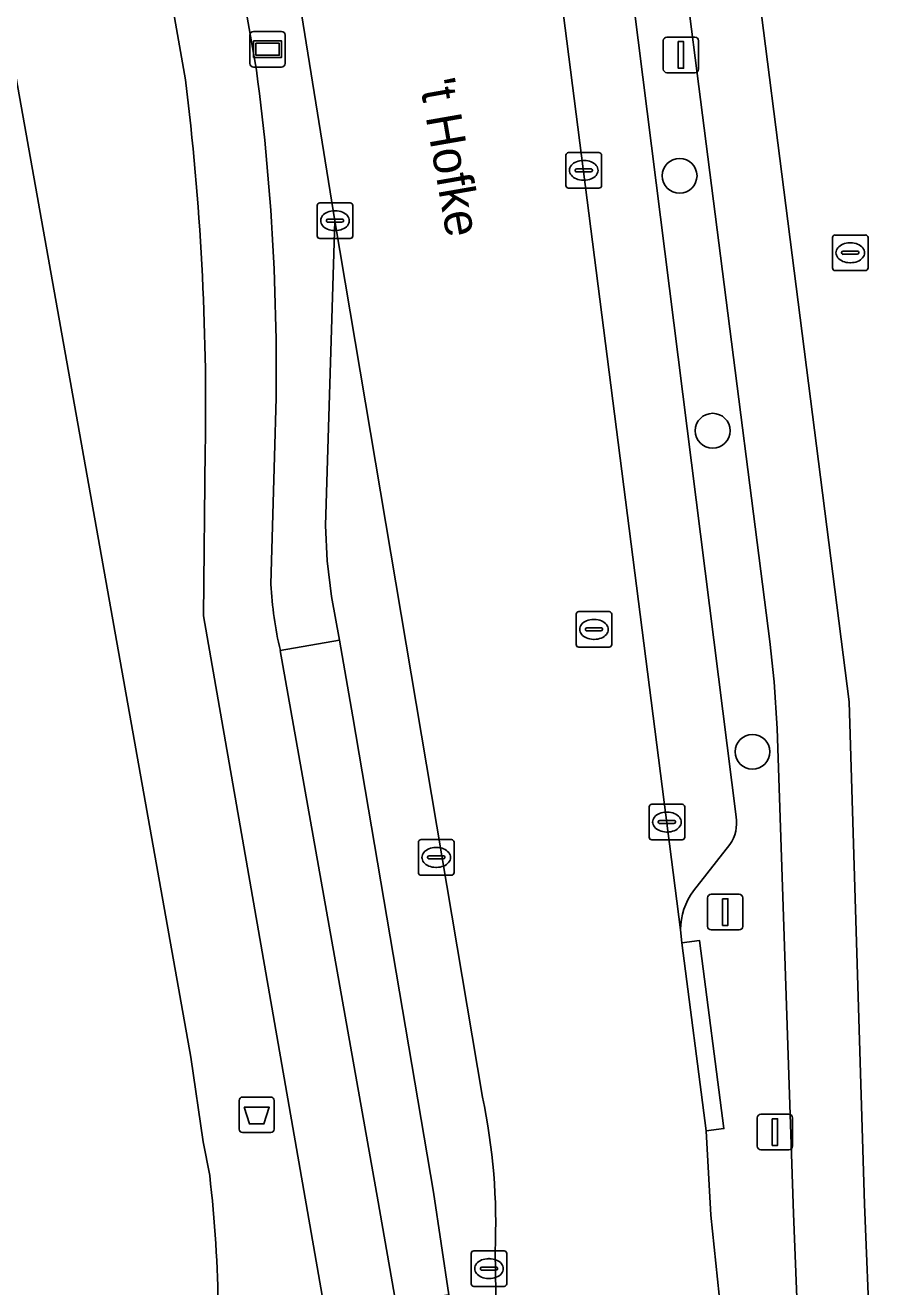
# Model space of a CAD drawing. Extents: x 162879 to 165540, y 384011 to 385181.
# Drawn here: x 164067.28 to 164091.19, y 384371.44 to 384406.9 of the extents above; entities that cross this region are included whole.
import ezdxf

# ---------------------------------------------------------------- set-up
doc = ezdxf.new("R2010")
doc.units = 0
for name, color, linetype in [('IMGEO_Afvalbak', 7, 'Continuous'), ('IMGEO_Boom', 7, 'Continuous'), ('IMGEO_Brandkraan', 7, 'Continuous'), ('IMGEO_Erf', 7, 'Continuous'), ('IMGEO_Fietspad_gesloten', 7, 'Continuous'), ('IMGEO_Kolk', 7, 'Continuous'), ('IMGEO_Lichtmast', 7, 'Continuous'), ('IMGEO_Openbare_ruimte_label', 7, 'Continuous'), ('IMGEO_Parkeervlak_open', 7, 'Continuous'), ('IMGEO_Rijbaan_lokaal_gesloten', 7, 'Continuous'), ('IMGEO_Rijbaan_lokaal_open', 7, 'Continuous'), ('IMGEO_Rioolput', 7, 'Continuous'), ('IMGEO_Verkeerseiland_open', 7, 'Continuous'), ('IMGEO_Verkeersregelinstallatiepaal', 7, 'Continuous'), ('IMGEO_Voetpad_open', 7, 'Continuous'), ('IMGEO_Wegwijzer', 7, 'Continuous')]:
    doc.layers.add(name, color=color, linetype=linetype)

msp = doc.modelspace()

# ---------------------------------------------------------------- linework, layer by layer
at = {"layer": 'IMGEO_Afvalbak'}
for p, q in [((164073.392, 384376.77), (164074.182, 384376.77)), ((164074.182, 384376.77), (164073.392, 384376.77)), ((164073.292, 384375.87), (164073.292, 384376.67)), ((164073.292, 384376.67), (164073.292, 384375.87)), ((164074.282, 384376.67), (164074.282, 384375.87)), ((164074.282, 384375.87), (164074.282, 384376.67)), ((164074.182, 384375.77), (164073.392, 384375.77)), ((164073.392, 384375.77), (164074.182, 384375.77))]:
    msp.add_line(p, q, dxfattribs=at)
msp.add_lwpolyline([(164073.435, 384376.484), (164074.139, 384376.484), (164073.99, 384376.014), (164073.584, 384376.014), (164073.435, 384376.484)], dxfattribs=at)
for centre, start, end in [((164073.392, 384376.67), 90, 180), ((164073.392, 384376.67), 90, 180), ((164074.182, 384376.67), 0, 90), ((164074.182, 384376.67), 360, 90), ((164073.392, 384375.87), 180, 270), ((164073.392, 384375.87), 180, 270), ((164074.182, 384375.87), 270, 0), ((164074.182, 384375.87), 270, 0)]:
    msp.add_arc(centre, 0.1, start, end, dxfattribs=at)
at = {"layer": 'IMGEO_Boom'}
for centre in [(164085.677, 384402.67), (164086.606, 384395.503), (164087.725, 384386.477)]:
    msp.add_circle(centre, 0.489, dxfattribs=at)
at = {"layer": 'IMGEO_Brandkraan'}
for p, q in [((164089.973, 384400.079), (164089.973, 384400.931)), ((164090.048, 384401.005), (164090.9, 384401.005)), ((164090.974, 384400.931), (164090.974, 384400.079)), ((164090.232, 384400.499), (164090.232, 384400.511)), ((164090.275, 384400.548), (164090.673, 384400.548)), ((164090.461, 384400.785), (164090.486, 384400.785)), ((164090.716, 384400.511), (164090.716, 384400.499)), ((164090.67, 384400.462), (164090.272, 384400.462)), ((164090.484, 384400.225), (164090.459, 384400.225)), ((164090.9, 384400.005), (164090.048, 384400.005))]:
    msp.add_line(p, q, dxfattribs=at)
for points in [[(164089.973, 384400.079), (164089.973, 384400.931)], [(164090.048, 384401.005), (164090.9, 384401.005)], [(164090.974, 384400.931), (164090.974, 384400.079)], [(164090.9, 384400.005), (164090.048, 384400.005)]]:
    msp.add_lwpolyline(points, dxfattribs=at)
for centre, radius, start, end in [((164090.05, 384400.929), 0.0765, 91.552, 178.448), ((164090.05, 384400.929), 0.0765, 91.552, 178.448), ((164090.898, 384400.929), 0.0765, 1.552, 88.448), ((164090.898, 384400.929), 0.0765, 1.552, 88.448), ((164090.272, 384400.508), 0.0403, 85.8775, 175.7526), ((164090.269, 384400.498), 0.0366, 178.938, 274.7102), ((164090.673, 384400.505), 0.043, 264.8664, 352.4533), ((164090.677, 384400.51), 0.0386, 1.7309, 96.639), ((164090.05, 384400.081), 0.0765, 181.552, 268.448), ((164090.05, 384400.081), 0.0765, 181.552, 268.448), ((164090.898, 384400.081), 0.0765, 271.552, 358.448), ((164090.898, 384400.081), 0.0765, 271.552, 358.448)]:
    msp.add_arc(centre, radius, start, end, dxfattribs=at)
for centre, major_axis, ratio, start_param, end_param in [((164090.46, 384400.505), (-0.387, 0.002), 0.722429, 4.712389, 7.853982), ((164090.485, 384400.505), (-0.39, 0.002), 0.717154, 1.570796, 4.712389)]:
    msp.add_ellipse(centre, major_axis=major_axis, ratio=ratio, start_param=start_param, end_param=end_param, dxfattribs=at)
at = {"layer": 'IMGEO_Erf'}
msp.add_lwpolyline([(164072.467, 384374.563), (164072.28, 384375.515), (164071.935, 384377.894), (164066.095, 384410.579)], dxfattribs=at)
msp.add_arc((164038.439, 384370.544), 34.264, 353.9227, 6.7367, dxfattribs=at)
at = {"layer": 'IMGEO_Fietspad_gesloten'}
for points in [[(164073.781, 384405.638), (164070.271, 384425.587), (164068.28, 384425.24), (164071.787, 384405.368)], [(164083.909, 384423.215), (164088.215, 384389.576), (164088.332, 384388.439), (164088.421, 384387.131), (164088.88, 384373.493), (164089.214, 384364.987), (164089.693, 384360.397), (164090.613, 384357.272), (164091.093, 384356.072)], [(164091.191, 384365.926), (164090.87, 384373.758), (164090.447, 384387.88), (164086.087, 384422.038)], [(164072.343, 384394.961), (164072.288, 384390.302), (164076.244, 384367.644), (164077.618, 384359.772), (164077.76, 384358.65), (164077.795, 384357.337)], [(164074.188, 384391.189), (164074.3, 384395.108)], [(164079.645, 384355.684), (164079.809, 384356.913), (164079.609, 384360.107), (164077.698, 384370.985), (164077.2, 384373.82), (164074.452, 384389.325)]]:
    msp.add_lwpolyline(points, dxfattribs=at)
for centre, radius, start, end in [((164010.853, 384397.259), 63.484, 358.05863, 7.58476), ((163997.018, 384396.155), 75.334, 359.0918, 7.02451), ((164084.638, 384391.718), 10.463, 182.8997, 193.2228)]:
    msp.add_arc(centre, radius, start, end, dxfattribs=at)
at = {"layer": 'IMGEO_Kolk'}
for p, q in [((164082.482, 384402.397), (164082.482, 384403.249)), ((164082.557, 384403.323), (164083.409, 384403.323)), ((164082.97, 384403.103), (164082.995, 384403.103)), ((164083.483, 384403.249), (164083.483, 384402.397)), ((164082.741, 384402.817), (164082.741, 384402.829)), ((164083.179, 384402.78), (164082.781, 384402.78)), ((164082.784, 384402.866), (164083.182, 384402.866)), ((164083.225, 384402.829), (164083.225, 384402.817)), ((164083.409, 384402.323), (164082.557, 384402.323)), ((164082.993, 384402.543), (164082.968, 384402.543)), ((164075.488, 384400.982), (164075.488, 384401.834)), ((164075.563, 384401.908), (164076.415, 384401.908)), ((164075.976, 384401.688), (164076.001, 384401.688)), ((164076.489, 384401.834), (164076.489, 384400.982)), ((164075.747, 384401.402), (164075.747, 384401.414)), ((164076.185, 384401.365), (164075.787, 384401.365)), ((164075.79, 384401.451), (164076.188, 384401.451)), ((164076.231, 384401.414), (164076.231, 384401.402)), ((164076.415, 384400.908), (164075.563, 384400.908)), ((164075.999, 384401.128), (164075.974, 384401.128)), ((164084.819, 384384.074), (164084.819, 384384.926)), ((164084.894, 384385), (164085.746, 384385)), ((164085.82, 384384.926), (164085.82, 384384.074)), ((164085.121, 384384.543), (164085.519, 384384.543)), ((164085.307, 384384.78), (164085.332, 384384.78)), ((164085.078, 384384.494), (164085.078, 384384.506)), ((164085.516, 384384.457), (164085.118, 384384.457)), ((164085.33, 384384.22), (164085.305, 384384.22)), ((164085.562, 384384.506), (164085.562, 384384.494)), ((164078.334, 384383.08), (164078.334, 384383.932)), ((164078.409, 384384.006), (164079.261, 384384.006)), ((164079.335, 384383.932), (164079.335, 384383.08)), ((164085.746, 384384), (164084.894, 384384)), ((164078.593, 384383.5), (164078.593, 384383.512)), ((164078.636, 384383.549), (164079.034, 384383.549)), ((164078.822, 384383.786), (164078.847, 384383.786)), ((164079.077, 384383.512), (164079.077, 384383.5)), ((164079.031, 384383.463), (164078.633, 384383.463)), ((164078.845, 384383.226), (164078.82, 384383.226)), ((164079.261, 384383.006), (164078.409, 384383.006)), ((164079.817, 384371.52), (164079.817, 384372.372)), ((164079.892, 384372.446), (164080.744, 384372.446)), ((164080.305, 384372.226), (164080.33, 384372.226)), ((164080.818, 384372.372), (164080.818, 384371.52)), ((164080.076, 384371.94), (164080.076, 384371.952)), ((164080.514, 384371.903), (164080.116, 384371.903)), ((164080.119, 384371.989), (164080.517, 384371.989)), ((164080.56, 384371.952), (164080.56, 384371.94)), ((164080.744, 384371.446), (164079.892, 384371.446)), ((164080.328, 384371.666), (164080.303, 384371.666))]:
    msp.add_line(p, q, dxfattribs=at)
for points in [[(164082.482, 384402.397), (164082.482, 384403.249)], [(164082.557, 384403.323), (164083.409, 384403.323)], [(164083.483, 384403.249), (164083.483, 384402.397)], [(164083.409, 384402.323), (164082.557, 384402.323)], [(164075.488, 384400.982), (164075.488, 384401.834)], [(164075.563, 384401.908), (164076.415, 384401.908)], [(164076.489, 384401.834), (164076.489, 384400.982)], [(164076.415, 384400.908), (164075.563, 384400.908)], [(164084.819, 384384.074), (164084.819, 384384.926)], [(164084.894, 384385), (164085.746, 384385)], [(164085.82, 384384.926), (164085.82, 384384.074)], [(164078.334, 384383.08), (164078.334, 384383.932)], [(164078.409, 384384.006), (164079.261, 384384.006)], [(164079.335, 384383.932), (164079.335, 384383.08)], [(164085.746, 384384), (164084.894, 384384)], [(164079.261, 384383.006), (164078.409, 384383.006)], [(164079.817, 384371.52), (164079.817, 384372.372)], [(164079.892, 384372.446), (164080.744, 384372.446)], [(164080.818, 384372.372), (164080.818, 384371.52)], [(164080.744, 384371.446), (164079.892, 384371.446)]]:
    msp.add_lwpolyline(points, dxfattribs=at)
for centre, radius, start, end in [((164082.559, 384403.247), 0.0765, 91.552, 178.448), ((164082.559, 384403.247), 0.0765, 91.552, 178.448), ((164083.407, 384403.247), 0.0765, 1.552, 88.448), ((164083.407, 384403.247), 0.0765, 1.552, 88.448), ((164082.781, 384402.826), 0.0403, 85.8775, 175.7526), ((164082.778, 384402.816), 0.0366, 178.938, 274.7102), ((164083.182, 384402.823), 0.043, 264.8664, 352.4533), ((164083.186, 384402.828), 0.0386, 1.7309, 96.639), ((164082.559, 384402.399), 0.0765, 181.552, 268.448), ((164082.559, 384402.399), 0.0765, 181.552, 268.448), ((164083.407, 384402.399), 0.0765, 271.552, 358.448), ((164083.407, 384402.399), 0.0765, 271.552, 358.448), ((164075.565, 384401.832), 0.0765, 91.552, 178.448), ((164075.565, 384401.832), 0.0765, 91.552, 178.448), ((164076.413, 384401.832), 0.0765, 1.552, 88.448), ((164076.413, 384401.832), 0.0765, 1.552, 88.448), ((164075.787, 384401.411), 0.0403, 85.8775, 175.7526), ((164075.784, 384401.401), 0.0366, 178.938, 274.7102), ((164076.188, 384401.408), 0.043, 264.8664, 352.4533), ((164076.192, 384401.413), 0.0386, 1.7309, 96.639), ((164075.565, 384400.984), 0.0765, 181.552, 268.448), ((164075.565, 384400.984), 0.0765, 181.552, 268.448), ((164076.413, 384400.984), 0.0765, 271.552, 358.448), ((164076.413, 384400.984), 0.0765, 271.552, 358.448), ((164084.896, 384384.924), 0.0765, 91.552, 178.448), ((164084.896, 384384.924), 0.0765, 91.552, 178.448), ((164085.744, 384384.924), 0.0765, 1.552, 88.448), ((164085.744, 384384.924), 0.0765, 1.552, 88.448), ((164085.118, 384384.503), 0.0403, 85.8775, 175.7526), ((164085.523, 384384.505), 0.0386, 1.7309, 96.639), ((164085.115, 384384.493), 0.0366, 178.938, 274.7102), ((164085.519, 384384.5), 0.043, 264.8664, 352.4533), ((164078.411, 384383.93), 0.0765, 91.552, 178.448), ((164078.411, 384383.93), 0.0765, 91.552, 178.448), ((164079.259, 384383.93), 0.0765, 1.552, 88.448), ((164079.259, 384383.93), 0.0765, 1.552, 88.448), ((164084.896, 384384.076), 0.0765, 181.552, 268.448), ((164084.896, 384384.076), 0.0765, 181.552, 268.448), ((164085.744, 384384.076), 0.0765, 271.552, 358.448), ((164085.744, 384384.076), 0.0765, 271.552, 358.448), ((164078.633, 384383.509), 0.0403, 85.8775, 175.7526), ((164078.63, 384383.499), 0.0366, 178.938, 274.7102), ((164079.034, 384383.506), 0.043, 264.8664, 352.4533), ((164079.038, 384383.511), 0.0386, 1.7309, 96.639), ((164078.411, 384383.082), 0.0765, 181.552, 268.448), ((164078.411, 384383.082), 0.0765, 181.552, 268.448), ((164079.259, 384383.082), 0.0765, 271.552, 358.448), ((164079.259, 384383.082), 0.0765, 271.552, 358.448), ((164079.894, 384372.37), 0.0765, 91.552, 178.448), ((164079.894, 384372.37), 0.0765, 91.552, 178.448), ((164080.742, 384372.37), 0.0765, 1.552, 88.448), ((164080.742, 384372.37), 0.0765, 1.552, 88.448), ((164080.116, 384371.949), 0.0403, 85.8775, 175.7526), ((164080.113, 384371.939), 0.0366, 178.938, 274.7102), ((164080.517, 384371.946), 0.043, 264.8664, 352.4533), ((164080.521, 384371.951), 0.0386, 1.7309, 96.639), ((164079.894, 384371.522), 0.0765, 181.552, 268.448), ((164079.894, 384371.522), 0.0765, 181.552, 268.448), ((164080.742, 384371.522), 0.0765, 271.552, 358.448), ((164080.742, 384371.522), 0.0765, 271.552, 358.448)]:
    msp.add_arc(centre, radius, start, end, dxfattribs=at)
for centre, major_axis, ratio, start_param, end_param in [((164082.969, 384402.823), (-0.387, 0.002), 0.722429, 4.712389, 7.853982), ((164082.994, 384402.823), (-0.39, 0.002), 0.717154, 1.570796, 4.712389), ((164075.975, 384401.408), (-0.387, 0.002), 0.722429, 4.712389, 7.853982), ((164076, 384401.408), (-0.39, 0.002), 0.717154, 1.570796, 4.712389), ((164085.306, 384384.5), (-0.387, 0.002), 0.722429, 4.712389, 7.853982), ((164085.331, 384384.5), (-0.39, 0.002), 0.717154, 1.570796, 4.712389), ((164078.821, 384383.506), (-0.387, 0.002), 0.722429, 4.712389, 7.853982), ((164078.846, 384383.506), (-0.39, 0.002), 0.717154, 1.570796, 4.712389), ((164080.304, 384371.946), (-0.387, 0.002), 0.722429, 4.712389, 7.853982), ((164080.329, 384371.946), (-0.39, 0.002), 0.717154, 1.570796, 4.712389)]:
    msp.add_ellipse(centre, major_axis=major_axis, ratio=ratio, start_param=start_param, end_param=end_param, dxfattribs=at)
at = {"layer": 'IMGEO_Lichtmast'}
for p, q in [((164085.319, 384406.568), (164086.109, 384406.568)), ((164086.109, 384406.568), (164085.319, 384406.568)), ((164085.219, 384405.668), (164085.219, 384406.468)), ((164085.219, 384406.468), (164085.219, 384405.668)), ((164086.209, 384406.468), (164086.209, 384405.668)), ((164086.209, 384405.668), (164086.209, 384406.468)), ((164086.109, 384405.568), (164085.319, 384405.568)), ((164085.319, 384405.568), (164086.109, 384405.568)), ((164087.861, 384375.386), (164087.861, 384376.186)), ((164087.861, 384376.186), (164087.861, 384375.386)), ((164087.961, 384376.286), (164088.751, 384376.286)), ((164088.751, 384376.286), (164087.961, 384376.286)), ((164088.851, 384376.186), (164088.851, 384375.386)), ((164088.851, 384375.386), (164088.851, 384376.186)), ((164088.751, 384375.286), (164087.961, 384375.286)), ((164087.961, 384375.286), (164088.751, 384375.286))]:
    msp.add_line(p, q, dxfattribs=at)
for points in [[(164085.639, 384406.443), (164085.789, 384406.443), (164085.789, 384405.693), (164085.639, 384405.693), (164085.639, 384406.443)], [(164088.281, 384376.161), (164088.431, 384376.161), (164088.431, 384375.411), (164088.281, 384375.411), (164088.281, 384376.161)]]:
    msp.add_lwpolyline(points, dxfattribs=at)
for centre, start, end in [((164085.319, 384406.468), 90, 180), ((164085.319, 384406.468), 90, 180), ((164086.109, 384406.468), 0, 90), ((164086.109, 384406.468), 360, 90), ((164085.319, 384405.668), 180, 270), ((164085.319, 384405.668), 180, 270), ((164086.109, 384405.668), 270, 0), ((164086.109, 384405.668), 270, 0), ((164087.961, 384376.186), 90, 180), ((164087.961, 384376.186), 90, 180), ((164088.751, 384376.186), 0, 90), ((164088.751, 384376.186), 360, 90), ((164087.961, 384375.386), 180, 270), ((164087.961, 384375.386), 180, 270), ((164088.751, 384375.386), 270, 0), ((164088.751, 384375.386), 270, 0)]:
    msp.add_arc(centre, 0.1, start, end, dxfattribs=at)
at = {"layer": 'IMGEO_Parkeervlak_open'}
for points in [[(164080.607, 384421.336), (164085.705, 384381.473)], [(164087.267, 384384.65), (164083.012, 384418.373)], [(164086.071, 384382.565), (164087.086, 384383.867)]]:
    msp.add_lwpolyline(points, dxfattribs=at)
for centre, radius, start, end in [((164086.212, 384384.481), 1.068, 324.8826, 9.0855), ((164087.483, 384381.484), 1.778, 142.5768, 180.3646)]:
    msp.add_arc(centre, radius, start, end, dxfattribs=at)
at = {"layer": 'IMGEO_Rijbaan_lokaal_gesloten'}
for points in [[(164071.827, 384426.866), (164071.993, 384425.884), (164073.176, 384418.869), (164075.989, 384401.408), (164080.136, 384376.77)], [(164080.489, 384372.432), (164080.558, 384368.374), (164087.023, 384368.952), (164086.558, 384373.446), (164086.427, 384375.821), (164085.739, 384381.108), (164085.705, 384381.473), (164080.607, 384421.336)]]:
    msp.add_lwpolyline(points, dxfattribs=at)
msp.add_arc((164063.395, 384373.224), 17.112, 357.346, 11.9582, dxfattribs=at)
at = {"layer": 'IMGEO_Rijbaan_lokaal_open'}
for points in [[(164075.989, 384401.408), (164075.722, 384392.841), (164075.765, 384391.847), (164075.895, 384390.844), (164076.113, 384389.61), (164076.492, 384387.459), (164078.76, 384374.096), (164079.187, 384371.205), (164079.617, 384368.29), (164080.558, 384368.374), (164080.489, 384372.432)], [(164080.136, 384376.77), (164075.989, 384401.408)]]:
    msp.add_lwpolyline(points, dxfattribs=at)
msp.add_arc((164063.395, 384373.224), 17.112, 357.346, 11.9582, dxfattribs=at)
at = {"layer": 'IMGEO_Rioolput'}
for p, q in [((164082.768, 384389.491), (164082.768, 384390.343)), ((164082.843, 384390.417), (164083.695, 384390.417)), ((164083.769, 384390.343), (164083.769, 384389.491)), ((164083.027, 384389.911), (164083.027, 384389.923)), ((164083.465, 384389.874), (164083.067, 384389.874)), ((164083.07, 384389.96), (164083.468, 384389.96)), ((164083.256, 384390.197), (164083.281, 384390.197)), ((164083.511, 384389.923), (164083.511, 384389.911)), ((164083.279, 384389.637), (164083.254, 384389.637)), ((164083.695, 384389.417), (164082.843, 384389.417))]:
    msp.add_line(p, q, dxfattribs=at)
for points in [[(164082.768, 384389.491), (164082.768, 384390.343)], [(164082.843, 384390.417), (164083.695, 384390.417)], [(164083.769, 384390.343), (164083.769, 384389.491)], [(164083.695, 384389.417), (164082.843, 384389.417)]]:
    msp.add_lwpolyline(points, dxfattribs=at)
for centre, radius, start, end in [((164082.845, 384390.341), 0.0765, 91.552, 178.448), ((164082.845, 384390.341), 0.0765, 91.552, 178.448), ((164083.693, 384390.341), 0.0765, 1.552, 88.448), ((164083.693, 384390.341), 0.0765, 1.552, 88.448), ((164083.067, 384389.92), 0.0403, 85.8775, 175.7526), ((164083.064, 384389.91), 0.0366, 178.938, 274.7102), ((164083.468, 384389.917), 0.043, 264.8664, 352.4533), ((164083.472, 384389.922), 0.0386, 1.7309, 96.639), ((164082.845, 384389.493), 0.0765, 181.552, 268.448), ((164082.845, 384389.493), 0.0765, 181.552, 268.448), ((164083.693, 384389.493), 0.0765, 271.552, 358.448), ((164083.693, 384389.493), 0.0765, 271.552, 358.448)]:
    msp.add_arc(centre, radius, start, end, dxfattribs=at)
for centre, major_axis, ratio, start_param, end_param in [((164083.255, 384389.917), (-0.387, 0.002), 0.722429, 4.712389, 7.853982), ((164083.28, 384389.917), (-0.39, 0.002), 0.717154, 1.570796, 4.712389)]:
    msp.add_ellipse(centre, major_axis=major_axis, ratio=ratio, start_param=start_param, end_param=end_param, dxfattribs=at)
at = {"layer": 'IMGEO_Verkeerseiland_open'}
for points in [[(164071.5, 384425.801), (164070.271, 384425.587), (164073.781, 384405.638)], [(164074.452, 384389.325), (164076.113, 384389.61), (164075.895, 384390.844), (164075.765, 384391.847), (164075.722, 384392.841), (164075.989, 384401.408), (164073.176, 384418.869), (164072.683, 384418.786), (164071.5, 384425.801)], [(164085.705, 384381.473), (164085.739, 384381.108), (164086.234, 384381.172), (164086.922, 384375.885), (164086.427, 384375.821), (164086.558, 384373.446), (164087.023, 384368.952), (164087.16, 384367.013), (164087.325, 384364.879), (164089.214, 384364.987), (164088.88, 384373.493), (164088.421, 384387.131), (164088.332, 384388.439), (164088.215, 384389.576), (164083.909, 384423.215)], [(164083.012, 384418.373), (164087.267, 384384.65)], [(164074.3, 384395.108), (164074.188, 384391.189)], [(164087.086, 384383.867), (164086.071, 384382.565)]]:
    msp.add_lwpolyline(points, dxfattribs=at)
for centre, radius, start, end in [((164010.853, 384397.259), 63.484, 358.05863, 7.58476), ((164084.638, 384391.718), 10.463, 182.8997, 193.2228), ((164086.212, 384384.481), 1.068, 324.8826, 9.0855), ((164087.483, 384381.484), 1.778, 142.5768, 180.3646)]:
    msp.add_arc(centre, radius, start, end, dxfattribs=at)
at = {"layer": 'IMGEO_Verkeersregelinstallatiepaal'}
for p, q in [((164086.564, 384382.469), (164087.354, 384382.469)), ((164087.354, 384382.469), (164086.564, 384382.469)), ((164086.464, 384381.569), (164086.464, 384382.369)), ((164086.464, 384382.369), (164086.464, 384381.569)), ((164087.454, 384382.369), (164087.454, 384381.569)), ((164087.454, 384381.569), (164087.454, 384382.369)), ((164087.354, 384381.469), (164086.564, 384381.469)), ((164086.564, 384381.469), (164087.354, 384381.469))]:
    msp.add_line(p, q, dxfattribs=at)
msp.add_lwpolyline([(164086.884, 384382.344), (164087.034, 384382.344), (164087.034, 384381.594), (164086.884, 384381.594), (164086.884, 384382.344)], dxfattribs=at)
for centre, start, end in [((164086.564, 384382.369), 90, 180), ((164086.564, 384382.369), 90, 180), ((164087.354, 384382.369), 0, 90), ((164087.354, 384382.369), 360, 90), ((164086.564, 384381.569), 180, 270), ((164086.564, 384381.569), 180, 270), ((164087.354, 384381.569), 270, 0), ((164087.354, 384381.569), 270, 0)]:
    msp.add_arc(centre, 0.1, start, end, dxfattribs=at)
at = {"layer": 'IMGEO_Voetpad_open'}
for points in [[(164071.787, 384405.368), (164068.28, 384425.24), (164064.4, 384424.602), (164058.592, 384423.535)], [(164060.807, 384423.081), (164063.207, 384423.506), (164063.848, 384423.62), (164064.68, 384418.793), (164064.546, 384418.769), (164064.62, 384418.336), (164065.007, 384416.237), (164065.291, 384414.696), (164064.66, 384414.507), (164064.744, 384414.199), (164065.081, 384414.33), (164066.095, 384410.579), (164071.935, 384377.894), (164072.28, 384375.515), (164072.467, 384374.563)], [(164086.087, 384422.038), (164090.447, 384387.88), (164090.87, 384373.758), (164091.191, 384365.926)], [(164075.958, 384367.627), (164076.244, 384367.644), (164072.288, 384390.302), (164072.343, 384394.961)]]:
    msp.add_lwpolyline(points, dxfattribs=at)
for points in [[(164076.492, 384387.459), (164076.113, 384389.61), (164074.452, 384389.325), (164077.2, 384373.82), (164077.698, 384370.985), (164079.187, 384371.205), (164078.76, 384374.096)], [(164086.427, 384375.821), (164086.922, 384375.885), (164086.234, 384381.172), (164085.739, 384381.108)]]:
    msp.add_lwpolyline(points, close=True, dxfattribs=at)
for centre, radius, start, end in [((163997.018, 384396.155), 75.334, 359.0918, 7.02451), ((164038.439, 384370.544), 34.264, 353.9227, 6.7367)]:
    msp.add_arc(centre, radius, start, end, dxfattribs=at)
at = {"layer": 'IMGEO_Wegwijzer'}
for p, q in [((164073.598, 384405.828), (164073.598, 384406.628)), ((164073.598, 384406.628), (164073.598, 384405.828)), ((164073.698, 384406.728), (164074.488, 384406.728)), ((164074.488, 384406.728), (164073.698, 384406.728)), ((164074.588, 384406.628), (164074.588, 384405.828)), ((164074.588, 384405.828), (164074.588, 384406.628)), ((164074.488, 384405.728), (164073.698, 384405.728)), ((164073.698, 384405.728), (164074.488, 384405.728))]:
    msp.add_line(p, q, dxfattribs=at)
for points in [[(164073.699, 384406.46), (164074.487, 384406.46), (164074.487, 384405.996), (164073.699, 384405.996), (164073.699, 384406.46)], [(164073.764, 384406.395), (164073.764, 384406.061), (164074.422, 384406.061), (164074.422, 384406.395), (164073.764, 384406.395)]]:
    msp.add_lwpolyline(points, dxfattribs=at)
for centre, start, end in [((164073.698, 384406.628), 90, 180), ((164073.698, 384406.628), 90, 180), ((164074.488, 384406.628), 0, 90), ((164074.488, 384406.628), 360, 90), ((164073.698, 384405.828), 180, 270), ((164073.698, 384405.828), 180, 270), ((164074.488, 384405.828), 270, 0), ((164074.488, 384405.828), 270, 0)]:
    msp.add_arc(centre, 0.1, start, end, dxfattribs=at)

# ---------------------------------------------------------------- texts
at = {"layer": 'IMGEO_Openbare_ruimte_label'}
msp.add_text("'t Hofke", height=1, rotation=279.9051, dxfattribs=at).set_placement((164078.364, 384405.321))

doc.saveas('drawing.dxf')
